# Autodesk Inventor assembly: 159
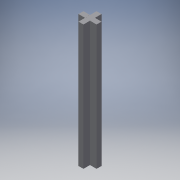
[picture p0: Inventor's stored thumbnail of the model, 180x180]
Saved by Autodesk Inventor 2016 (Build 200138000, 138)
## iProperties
Created: 2016-06
Part Number: 159
Material: Genérico
Document SubType Name: Assembly
Designer: adm
Author: adm
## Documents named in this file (2)
- C:\Users\adm\Desktop\proyecto del profe. valcarcel\trabajo3\159.iam
- C:\Users\adm\Desktop\proyecto del profe. valcarcel\trabajo3\eje.ipt
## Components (2 placed, 1 different names)
1. eje:1 — Coincidencia:1, Coincidencia:2, Coincidencia:3
2. eje:2 — Coincidencia:1, Coincidencia:2, Coincidencia:3
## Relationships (3: Mate 3)
- Coincidencia:1 [Mate]: eje:1 ↔ eje:2
- Coincidencia:2 [Mate]: eje:1 ↔ eje:2
- Coincidencia:3 [Mate]: eje:1 ↔ eje:2
